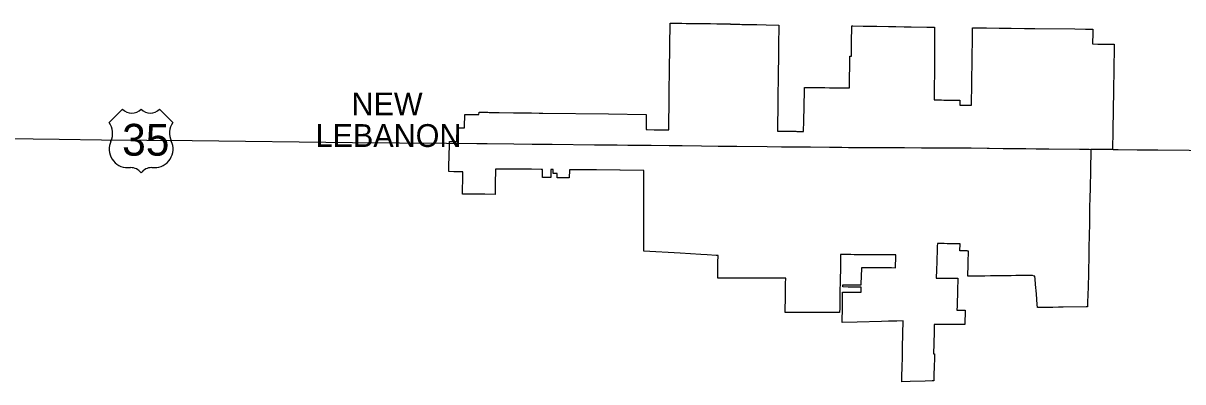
# Model space of a CAD drawing. Extents: x 0 to 34, y 0 to 22.
# Drawn here: x 4.0908 to 4.4993, y 15.0222 to 15.1484 of the extents above; entities that cross this region are included whole.
import ezdxf

# ---------------------------------------------------------------- set-up
doc = ezdxf.new("R2010")
doc.units = 0
for name, color, linetype in [('GM_X_Corporation', 7, 'Continuous'), ('GM_X_Corporation_Text', 7, 'Continuous'), ('GM_X_US_Location', 7, 'Continuous'), ('GM_X_US_Route', 7, 'Continuous'), ('GM_X_US_Shield', 7, 'Continuous')]:
    doc.layers.add(name, color=color, linetype=linetype)

msp = doc.modelspace()

# ---------------------------------------------------------------- linework, layer by layer
at = {"layer": 'GM_X_Corporation'}
for points in [[(4.409102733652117, 15.147058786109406), (4.4118993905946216, 15.147003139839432), (4.411898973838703, 15.146904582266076), (4.411895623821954, 15.146369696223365), (4.411868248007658, 15.141996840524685), (4.411827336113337, 15.135460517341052), (4.41182143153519, 15.134461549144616), (4.411809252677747, 15.132402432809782), (4.411807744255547, 15.132158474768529), (4.411787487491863, 15.128883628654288), (4.411783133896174, 15.12817898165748), (4.411764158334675, 15.125138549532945), (4.411740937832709, 15.121417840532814), (4.411941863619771, 15.121415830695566), (4.4125311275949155, 15.121410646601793), (4.412741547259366, 15.121408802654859), (4.4135492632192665, 15.121401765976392), (4.413945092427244, 15.121397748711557), (4.414198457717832, 15.121395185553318), (4.414342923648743, 15.121393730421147), (4.415142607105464, 15.121386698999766), (4.41594228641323, 15.121379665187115), (4.41674197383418, 15.121372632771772), (4.417143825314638, 15.121368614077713), (4.417395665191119, 15.121366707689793), (4.41754165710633, 15.121365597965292), (4.4183413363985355, 15.12135856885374), (4.419143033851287, 15.121351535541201), (4.419544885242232, 15.121347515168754), (4.419942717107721, 15.121344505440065), (4.420742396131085, 15.121337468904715), (4.420742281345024, 15.121324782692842), (4.420726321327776, 15.119569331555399), (4.42160638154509, 15.11956128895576), (4.42192786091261, 15.119558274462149), (4.423133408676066, 15.119547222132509), (4.424823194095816, 15.119532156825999), (4.424848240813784, 15.122168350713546), (4.424855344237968, 15.122915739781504), (4.424919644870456, 15.122915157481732), (4.4249377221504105, 15.124075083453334), (4.42494925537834, 15.124795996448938), (4.4249505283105, 15.124875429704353), (4.424963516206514, 15.125687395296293), (4.424971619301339, 15.126193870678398), (4.424985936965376, 15.127088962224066), (4.425019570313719, 15.129191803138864), (4.425050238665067, 15.131109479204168), (4.425067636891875, 15.132237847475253), (4.425084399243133, 15.133324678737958), (4.425087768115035, 15.133560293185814), (4.425129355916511, 15.136468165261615), (4.425149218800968, 15.13785689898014), (4.425200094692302, 15.141413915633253), (4.4252264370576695, 15.143255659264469), (4.42524327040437, 15.144432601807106), (4.425254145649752, 15.145192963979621), (4.425277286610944, 15.146810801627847), (4.429326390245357, 15.146763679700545), (4.430103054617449, 15.14675464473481), (4.434657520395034, 15.14670164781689), (4.436739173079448, 15.146677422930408), (4.4388668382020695, 15.14665266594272), (4.443565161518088, 15.146597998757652), (4.445248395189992, 15.146578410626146), (4.447224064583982, 15.146555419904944), (4.461262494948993, 15.14639207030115), (4.465061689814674, 15.14634785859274), (4.467322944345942, 15.146321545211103), (4.467588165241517, 15.14631852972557), (4.467588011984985, 15.146305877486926), (4.467559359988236, 15.143910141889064), (4.467540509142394, 15.14233376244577), (4.46752587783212, 15.141110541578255), (4.469394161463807, 15.141091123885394), (4.469748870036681, 15.141087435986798), (4.470945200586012, 15.14107500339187), (4.472689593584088, 15.14105686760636), (4.475161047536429, 15.141031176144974), (4.475160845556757, 15.141018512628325), (4.475105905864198, 15.137552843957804), (4.475061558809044, 15.134755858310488), (4.47499135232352, 15.130327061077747), (4.47493238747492, 15.126607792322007), (4.4748793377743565, 15.123261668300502), (4.474870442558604, 15.122700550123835), (4.474824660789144, 15.119812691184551), (4.474797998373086, 15.118131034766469), (4.474791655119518, 15.117730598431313), (4.474684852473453, 15.11099382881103), (4.474662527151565, 15.109575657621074), (4.474588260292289, 15.104855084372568), (4.474584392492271, 15.104523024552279), (4.474573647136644, 15.1039300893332), (4.470868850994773, 15.103952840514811), (4.4692145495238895, 15.103962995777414), (4.467061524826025, 15.103986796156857), (4.4669271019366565, 15.10397561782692), (4.466922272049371, 15.103717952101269), (4.466915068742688, 15.103333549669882), (4.466878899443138, 15.101566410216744), (4.466872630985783, 15.101244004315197), (4.466834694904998, 15.099292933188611), (4.466805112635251, 15.097821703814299), (4.466631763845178, 15.089200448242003), (4.466610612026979, 15.088141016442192), (4.466499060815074, 15.082553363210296), (4.466459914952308, 15.080592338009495), (4.466456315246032, 15.080411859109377), (4.466406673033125, 15.077925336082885), (4.4662371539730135, 15.069433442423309), (4.466148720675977, 15.065003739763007), (4.466096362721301, 15.062381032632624), (4.466062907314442, 15.060705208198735), (4.466045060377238, 15.059811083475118), (4.465835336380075, 15.052379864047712), (4.465788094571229, 15.050706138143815), (4.465735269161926, 15.048834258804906), (4.46572960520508, 15.048633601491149), (4.465229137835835, 15.048623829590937), (4.457139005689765, 15.048465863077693), (4.456993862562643, 15.04846312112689), (4.455491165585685, 15.048434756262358), (4.453471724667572, 15.048396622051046), (4.448133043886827, 15.04829582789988), (4.448122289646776, 15.048427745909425), (4.4481147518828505, 15.048520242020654), (4.448053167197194, 15.049275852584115), (4.447738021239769, 15.053142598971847), (4.44747095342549, 15.056419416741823), (4.447310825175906, 15.05838407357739), (4.447238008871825, 15.059277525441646), (4.447231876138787, 15.059352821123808), (4.447021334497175, 15.059349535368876), (4.446966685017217, 15.059348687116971), (4.446412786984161, 15.059631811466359), (4.444787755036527, 15.059612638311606), (4.443867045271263, 15.05960177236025), (4.441094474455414, 15.059569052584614), (4.440538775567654, 15.05956249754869), (4.438841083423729, 15.0595424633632), (4.435899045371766, 15.059507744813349), (4.434672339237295, 15.059493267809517), (4.431599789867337, 15.059457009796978), (4.429552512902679, 15.059432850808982), (4.426803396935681, 15.059400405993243), (4.424186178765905, 15.059369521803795), (4.423548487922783, 15.059361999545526), (4.423558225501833, 15.059651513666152), (4.423675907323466, 15.063212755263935), (4.423720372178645, 15.064661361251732), (4.423815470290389, 15.067759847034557), (4.423829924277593, 15.06823069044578), (4.423543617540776, 15.068237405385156), (4.423308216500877, 15.06824291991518), (4.420819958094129, 15.068296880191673), (4.420806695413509, 15.068297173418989), (4.4208951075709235, 15.070706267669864), (4.419755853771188, 15.070731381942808), (4.418614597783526, 15.070756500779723), (4.418092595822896, 15.07076752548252), (4.417473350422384, 15.070781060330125), (4.416332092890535, 15.07080610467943), (4.415190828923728, 15.070830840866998), (4.414049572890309, 15.070855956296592), (4.413781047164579, 15.070861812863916), (4.412852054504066, 15.070882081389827), (4.412818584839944, 15.069923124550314), (4.412775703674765, 15.068650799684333), (4.412769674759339, 15.068472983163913), (4.412765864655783, 15.068359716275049), (4.412733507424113, 15.067398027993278), (4.412691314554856, 15.066144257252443), (4.412689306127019, 15.066082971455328), (4.41267323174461, 15.065616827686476), (4.412649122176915, 15.064891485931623), (4.412618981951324, 15.06400942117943), (4.412606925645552, 15.063638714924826), (4.412564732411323, 15.06238494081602), (4.412522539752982, 15.06113217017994), (4.412500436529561, 15.060477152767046), (4.412480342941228, 15.059879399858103), (4.412438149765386, 15.058708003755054), (4.412637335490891, 15.058708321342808), (4.413468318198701, 15.05870963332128), (4.413560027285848, 15.058709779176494), (4.414212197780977, 15.058710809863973), (4.414956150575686, 15.05871199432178), (4.415758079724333, 15.058713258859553), (4.416560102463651, 15.058714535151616), (4.417439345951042, 15.058715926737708), (4.418703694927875, 15.058717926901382), (4.420053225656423, 15.05872006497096), (4.420081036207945, 15.058720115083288), (4.4200806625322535, 15.058707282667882), (4.420073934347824, 15.058476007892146), (4.420045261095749, 15.05749016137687), (4.420036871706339, 15.057201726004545), (4.420034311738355, 15.057113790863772), (4.419994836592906, 15.055756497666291), (4.419987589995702, 15.055507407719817), (4.419944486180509, 15.054025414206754), (4.4199162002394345, 15.05305286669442), (4.4198941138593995, 15.052293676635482), (4.4198584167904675, 15.051066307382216), (4.419847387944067, 15.050687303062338), (4.419822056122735, 15.049816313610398), (4.419794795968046, 15.048879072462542), (4.4197527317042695, 15.047432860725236), (4.419765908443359, 15.047432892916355), (4.420883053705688, 15.047435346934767), (4.421293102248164, 15.04743624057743), (4.422478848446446, 15.047435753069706), (4.422636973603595, 15.047436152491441), (4.422494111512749, 15.042315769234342), (4.422330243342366, 15.04232870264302), (4.42058036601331, 15.042330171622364), (4.41929396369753, 15.042331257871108), (4.41915709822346, 15.042331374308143), (4.4180075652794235, 15.042332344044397), (4.416721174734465, 15.042333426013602), (4.415434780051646, 15.042334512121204), (4.414146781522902, 15.042335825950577), (4.4117712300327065, 15.04233825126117), (4.411736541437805, 15.041088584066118), (4.411682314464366, 15.03913489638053), (4.4116043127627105, 15.036324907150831), (4.411598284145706, 15.036083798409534), (4.411587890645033, 15.035711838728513), (4.411483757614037, 15.031984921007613), (4.411855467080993, 15.031983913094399), (4.411799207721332, 15.029947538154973), (4.411746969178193, 15.028045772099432), (4.41173529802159, 15.027625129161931), (4.411654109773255, 15.024698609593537), (4.411632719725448, 15.023927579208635), (4.411594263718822, 15.022541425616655), (4.410997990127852, 15.02252319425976), (4.408604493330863, 15.022450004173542), (4.403270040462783, 15.022287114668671), (4.40034645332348, 15.022197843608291), (4.400380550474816, 15.023776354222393), (4.400386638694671, 15.024058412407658), (4.400459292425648, 15.027521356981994), (4.400527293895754, 15.030762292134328), (4.40057213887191, 15.032878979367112), (4.400603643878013, 15.03436588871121), (4.40079826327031, 15.043598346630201), (4.400798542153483, 15.043611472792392), (4.398609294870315, 15.043557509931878), (4.395666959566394, 15.04348497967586), (4.393132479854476, 15.043422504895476), (4.384600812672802, 15.043212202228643), (4.3792925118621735, 15.043081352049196), (4.3792794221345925, 15.043081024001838), (4.379304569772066, 15.044249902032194), (4.379321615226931, 15.045042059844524), (4.379393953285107, 15.046598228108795), (4.379400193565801, 15.046909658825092), (4.379452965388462, 15.04954267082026), (4.379470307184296, 15.050407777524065), (4.379448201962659, 15.051831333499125), (4.379468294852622, 15.053283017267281), (4.379476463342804, 15.053702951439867), (4.37947834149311, 15.053799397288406), (4.381937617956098, 15.053784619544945), (4.385065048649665, 15.053765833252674), (4.386000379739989, 15.053760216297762), (4.386042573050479, 15.055527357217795), (4.385124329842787, 15.055533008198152), (4.381468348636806, 15.055555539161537), (4.379533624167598, 15.055567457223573), (4.379520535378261, 15.05556754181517), (4.3795378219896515, 15.056335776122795), (4.379538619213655, 15.056371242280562), (4.381179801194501, 15.056361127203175), (4.385854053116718, 15.056332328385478), (4.386060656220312, 15.056331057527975), (4.3860660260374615, 15.056545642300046), (4.386141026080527, 15.059544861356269), (4.386201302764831, 15.061955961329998), (4.386213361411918, 15.062437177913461), (4.388081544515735, 15.06242584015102), (4.38949286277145, 15.062417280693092), (4.393310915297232, 15.062394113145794), (4.396751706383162, 15.062373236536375), (4.398132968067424, 15.062364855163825), (4.398138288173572, 15.062692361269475), (4.398144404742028, 15.063299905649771), (4.3981463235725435, 15.063490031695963), (4.398150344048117, 15.063817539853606), (4.398164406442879, 15.064942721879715), (4.398168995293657, 15.065309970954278), (4.398178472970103, 15.066067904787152), (4.3981885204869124, 15.066878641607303), (4.3972097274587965, 15.06688219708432), (4.396253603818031, 15.066885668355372), (4.395449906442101, 15.066888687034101), (4.394736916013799, 15.06689198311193), (4.394147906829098, 15.06689470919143), (4.3929644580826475, 15.066900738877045), (4.39273540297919, 15.066901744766), (4.3917830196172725, 15.06690676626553), (4.39060157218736, 15.066911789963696), (4.390528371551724, 15.066912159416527), (4.389418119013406, 15.066917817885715), (4.388236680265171, 15.06692384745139), (4.387053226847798, 15.06692987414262), (4.385871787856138, 15.066935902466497), (4.384690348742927, 15.066941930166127), (4.384044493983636, 15.066945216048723), (4.3835068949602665, 15.06694795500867), (4.382325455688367, 15.066953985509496), (4.381202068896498, 15.066959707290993), (4.381142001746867, 15.066960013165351), (4.37967926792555, 15.066967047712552), (4.379191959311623, 15.066960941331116), (4.378716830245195, 15.066954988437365), (4.3787169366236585, 15.066876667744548), (4.378718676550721, 15.065564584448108), (4.378722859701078, 15.062411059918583), (4.37871884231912, 15.06224328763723), (4.37871884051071, 15.06208957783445), (4.378714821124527, 15.0619087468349), (4.378692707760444, 15.061059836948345), (4.378686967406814, 15.060839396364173), (4.378652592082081, 15.059519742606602), (4.378632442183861, 15.058746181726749), (4.378632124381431, 15.058733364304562), (4.3785780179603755, 15.056538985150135), (4.378576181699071, 15.056464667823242), (4.3785440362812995, 15.055036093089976), (4.378529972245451, 15.054442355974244), (4.378511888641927, 15.053725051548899), (4.378503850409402, 15.05331717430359), (4.378491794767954, 15.052454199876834), (4.378483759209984, 15.051830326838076), (4.378505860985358, 15.050406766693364), (4.37848699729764, 15.049495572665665), (4.378485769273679, 15.04943629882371), (4.378485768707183, 15.04940415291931), (4.3784857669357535, 15.049354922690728), (4.378475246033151, 15.048821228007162), (4.3784747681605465, 15.048796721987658), (4.378463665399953, 15.048233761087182), (4.378463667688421, 15.048184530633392), (4.378463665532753, 15.048150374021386), (4.3784295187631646, 15.046596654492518), (4.3767156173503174, 15.046594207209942), (4.376140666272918, 15.046593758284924), (4.375429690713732, 15.046593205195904), (4.374736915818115, 15.04659266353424), (4.374143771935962, 15.04659219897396), (4.373285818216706, 15.046591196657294), (4.372857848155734, 15.04659018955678), (4.372384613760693, 15.046589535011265), (4.371411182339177, 15.046588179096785), (4.370607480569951, 15.046587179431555), (4.368678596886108, 15.046585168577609), (4.366347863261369, 15.046582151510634), (4.364017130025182, 15.046580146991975), (4.362135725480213, 15.046577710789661), (4.361686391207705, 15.04657713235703), (4.360062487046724, 15.046575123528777), (4.359260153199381, 15.04657412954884), (4.359247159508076, 15.04657411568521), (4.359259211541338, 15.04737380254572), (4.3592612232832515, 15.047459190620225), (4.35928712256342, 15.049166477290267), (4.359312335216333, 15.049971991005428), (4.35931547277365, 15.051078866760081), (4.359333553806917, 15.052284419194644), (4.359351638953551, 15.053489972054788), (4.359362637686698, 15.054174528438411), (4.359369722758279, 15.054615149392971), (4.35938981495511, 15.05594929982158), (4.359396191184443, 15.056374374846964), (4.359401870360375, 15.056752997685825), (4.359429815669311, 15.058669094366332), (4.359429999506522, 15.058681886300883), (4.358682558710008, 15.058682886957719), (4.356884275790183, 15.058683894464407), (4.354836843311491, 15.058685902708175), (4.352690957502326, 15.058687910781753), (4.351887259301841, 15.058688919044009), (4.3504426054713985, 15.058689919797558), (4.349202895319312, 15.058690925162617), (4.347965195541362, 15.058691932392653), (4.346197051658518, 15.0586929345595), (4.344869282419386, 15.058693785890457), (4.344637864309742, 15.058693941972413), (4.340078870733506, 15.05869695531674), (4.338543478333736, 15.058698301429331), (4.335497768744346, 15.058700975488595), (4.3355439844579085, 15.062911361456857), (4.335549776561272, 15.06338841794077), (4.335554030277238, 15.063602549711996), (4.33557412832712, 15.064888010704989), (4.335584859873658, 15.06592741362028), (4.335592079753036, 15.066626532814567), (4.335592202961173, 15.06663853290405), (4.335441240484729, 15.066647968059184), (4.3353510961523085, 15.066653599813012), (4.33494924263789, 15.066677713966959), (4.334949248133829, 15.06667816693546), (4.3317364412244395, 15.066874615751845), (4.3295776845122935, 15.067004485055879), (4.32585512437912, 15.067228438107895), (4.32226372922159, 15.067444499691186), (4.309469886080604, 15.068214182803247), (4.309469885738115, 15.07705249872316), (4.309466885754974, 15.089258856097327), (4.309461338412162, 15.090122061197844), (4.309442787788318, 15.093009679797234), (4.309430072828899, 15.09498782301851), (4.3094200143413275, 15.09655261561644), (4.301135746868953, 15.096651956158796), (4.301018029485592, 15.096653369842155), (4.292741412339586, 15.096752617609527), (4.2892687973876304, 15.096794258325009), (4.289172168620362, 15.096795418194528), (4.283243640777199, 15.096866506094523), (4.283242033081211, 15.096747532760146), (4.2832043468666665, 15.093962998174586), (4.279060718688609, 15.094025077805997), (4.2789130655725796, 15.094027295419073), (4.278930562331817, 15.095320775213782), (4.278932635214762, 15.095473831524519), (4.277630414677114, 15.095493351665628), (4.277487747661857, 15.095495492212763), (4.27749862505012, 15.09629913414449), (4.277505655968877, 15.09681845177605), (4.277507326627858, 15.096942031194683), (4.277376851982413, 15.096943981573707), (4.277105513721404, 15.096948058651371), (4.27701534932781, 15.096948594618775), (4.276743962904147, 15.096950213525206), (4.276703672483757, 15.096950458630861), (4.276702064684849, 15.096831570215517), (4.276694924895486, 15.096303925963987), (4.2766645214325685, 15.09405739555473), (4.27655721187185, 15.094058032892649), (4.273771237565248, 15.094074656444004), (4.2738091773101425, 15.096877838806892), (4.273810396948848, 15.096967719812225), (4.27327663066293, 15.096970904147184), (4.273238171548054, 15.09697113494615), (4.269911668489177, 15.096990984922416), (4.269875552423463, 15.09699120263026), (4.267862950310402, 15.097003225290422), (4.26634396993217, 15.097012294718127), (4.266307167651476, 15.097012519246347), (4.257164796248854, 15.097067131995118), (4.257163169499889, 15.096957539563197), (4.2571598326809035, 15.096734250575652), (4.257153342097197, 15.096299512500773), (4.257096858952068, 15.092517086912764), (4.257033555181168, 15.088183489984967), (4.253444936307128, 15.088240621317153), (4.252964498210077, 15.088243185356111), (4.250872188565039, 15.088254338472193), (4.2503979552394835, 15.08825686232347), (4.249910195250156, 15.088259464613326), (4.245573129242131, 15.088282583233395), (4.245687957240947, 15.09508188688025), (4.245704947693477, 15.096088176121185), (4.242652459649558, 15.09614100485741), (4.242572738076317, 15.09614238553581), (4.240752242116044, 15.096173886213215), (4.2407164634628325, 15.096174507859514), (4.2407642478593, 15.097989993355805), (4.240963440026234, 15.105557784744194), (4.24096725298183, 15.105702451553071), (4.24098121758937, 15.106233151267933), (4.2409951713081, 15.106763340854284), (4.24356433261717, 15.106763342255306), (4.243670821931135, 15.111616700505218), (4.244201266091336, 15.111611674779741), (4.245114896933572, 15.111603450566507), (4.246323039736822, 15.111592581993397), (4.246330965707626, 15.112025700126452), (4.246407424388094, 15.116202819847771), (4.2464086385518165, 15.11630015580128), (4.2464961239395, 15.116299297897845), (4.247636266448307, 15.116288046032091), (4.25033065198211, 15.116261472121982), (4.251388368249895, 15.11625104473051), (4.251406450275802, 15.117046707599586), (4.2514069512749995, 15.117094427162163), (4.254058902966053, 15.117058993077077), (4.254501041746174, 15.11705308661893), (4.2550234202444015, 15.117046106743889), (4.2576354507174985, 15.117011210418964), (4.2584988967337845, 15.11699967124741), (4.2635799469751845, 15.116931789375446), (4.264643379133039, 15.116917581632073), (4.264672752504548, 15.116917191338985), (4.265704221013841, 15.116903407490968), (4.266765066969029, 15.116889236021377), (4.26782188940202, 15.116875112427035), (4.269943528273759, 15.116846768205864), (4.2725935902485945, 15.116811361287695), (4.273853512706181, 15.116794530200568), (4.2970512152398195, 15.116484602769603), (4.310311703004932, 15.116307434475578), (4.310309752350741, 15.116163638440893), (4.310309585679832, 15.116150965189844), (4.3102394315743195, 15.110960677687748), (4.310628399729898, 15.110956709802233), (4.313053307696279, 15.110931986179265), (4.31459386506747, 15.110916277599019), (4.314673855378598, 15.110915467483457), (4.316303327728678, 15.110899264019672), (4.318210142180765, 15.110880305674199), (4.318226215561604, 15.112005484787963), (4.318353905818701, 15.121507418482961), (4.318386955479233, 15.123966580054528), (4.318426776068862, 15.12690423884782), (4.318460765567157, 15.12941186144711), (4.318484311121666, 15.131148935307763), (4.318528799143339, 15.134431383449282), (4.318569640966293, 15.137444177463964), (4.31862203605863, 15.14130990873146), (4.318643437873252, 15.14288870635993), (4.318684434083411, 15.145913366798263), (4.318713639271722, 15.148068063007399), (4.3187184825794, 15.148425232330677), (4.319164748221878, 15.148420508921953), (4.322840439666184, 15.148381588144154), (4.324405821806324, 15.148365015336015), (4.326314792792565, 15.148344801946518), (4.328707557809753, 15.148319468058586), (4.328965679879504, 15.148316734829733), (4.329820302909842, 15.148307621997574), (4.332923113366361, 15.148274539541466), (4.335181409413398, 15.148250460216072), (4.338126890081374, 15.148219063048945), (4.339969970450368, 15.1481994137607), (4.339990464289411, 15.148199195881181), (4.339990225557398, 15.148186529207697), (4.339988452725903, 15.148091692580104), (4.340001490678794, 15.148091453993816), (4.343237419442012, 15.148032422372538), (4.343936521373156, 15.148019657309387), (4.347688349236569, 15.147951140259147), (4.349316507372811, 15.147921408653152), (4.352496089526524, 15.147863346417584), (4.356990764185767, 15.147781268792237), (4.35699060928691, 15.147768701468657), (4.35690177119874, 15.140480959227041), (4.356846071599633, 15.13591182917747), (4.356835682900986, 15.135059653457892), (4.356802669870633, 15.132351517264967), (4.3567848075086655, 15.13088634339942), (4.356667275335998, 15.121245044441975), (4.356663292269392, 15.120919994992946), (4.356535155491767, 15.110461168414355), (4.356534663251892, 15.110421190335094), (4.356547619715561, 15.110421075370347), (4.36006915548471, 15.110389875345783), (4.360163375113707, 15.110389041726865), (4.3629583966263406, 15.11036439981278), (4.36335407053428, 15.110360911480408), (4.365716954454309, 15.110339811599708), (4.365801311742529, 15.114028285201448), (4.3658263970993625, 15.115125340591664), (4.365894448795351, 15.118100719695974), (4.365962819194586, 15.121090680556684), (4.366003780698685, 15.122899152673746), (4.366070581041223, 15.12584824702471), (4.37095106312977, 15.125779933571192), (4.373238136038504, 15.125747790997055), (4.374850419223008, 15.125725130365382), (4.377613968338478, 15.125686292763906), (4.38030701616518, 15.125648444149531), (4.381459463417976, 15.125632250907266), (4.381602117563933, 15.1256302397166), (4.3818410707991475, 15.125626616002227), (4.38186734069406, 15.125626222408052), (4.382028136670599, 15.136864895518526), (4.38227495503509, 15.136861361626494), (4.382577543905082, 15.136857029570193), (4.3826437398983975, 15.141483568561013), (4.382729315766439, 15.147464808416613), (4.382994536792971, 15.147460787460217), (4.383127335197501, 15.14745873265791), (4.3867478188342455, 15.147402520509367), (4.388220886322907, 15.147379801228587), (4.389769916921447, 15.147355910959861), (4.391568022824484, 15.147328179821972), (4.395641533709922, 15.14726582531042), (4.397212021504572, 15.147241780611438), (4.397336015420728, 15.147239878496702), (4.398233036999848, 15.147226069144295), (4.401153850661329, 15.14718111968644), (4.403624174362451, 15.147143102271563)], [(4.4118993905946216, 15.147003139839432), (4.411899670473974, 15.147015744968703), (4.411899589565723, 15.147003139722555)]]:
    msp.add_lwpolyline(points, close=True, dxfattribs=at)
at = {"layer": 'GM_X_US_Route'}
for p, q in [((4.239920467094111, 15.1061764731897), (4.250676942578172, 15.10608139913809)), ((4.250676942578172, 15.10608139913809), (4.254259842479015, 15.106043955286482)), ((4.329722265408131, 15.10525708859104), (4.335678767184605, 15.105194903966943)), ((4.379186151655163, 15.104766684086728), (4.38151603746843, 15.104721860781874)), ((4.466349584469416, 15.104063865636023), (4.474793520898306, 15.10394213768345))]:
    msp.add_line(p, q, dxfattribs=at)
for points in [[(4.085226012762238, 15.10779479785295), (4.103569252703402, 15.10757172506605), (4.118419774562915, 15.107399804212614), (4.150398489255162, 15.107085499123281), (4.206823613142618, 15.106469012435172), (4.239920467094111, 15.1061764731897)], [(4.254259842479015, 15.106043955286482), (4.263627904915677, 15.105946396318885), (4.27012817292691, 15.105878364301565), (4.273271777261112, 15.105881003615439), (4.277174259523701, 15.105855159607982), (4.2920696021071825, 15.105649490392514), (4.296513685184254, 15.10564579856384), (4.300062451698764, 15.105588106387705)], [(4.300062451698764, 15.105588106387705), (4.303780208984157, 15.105527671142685), (4.3069417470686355, 15.105494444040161), (4.3120803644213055, 15.105441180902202), (4.318381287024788, 15.105375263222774), (4.322999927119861, 15.105327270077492), (4.329722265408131, 15.10525708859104)], [(4.335678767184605, 15.105194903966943), (4.342269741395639, 15.10512634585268), (4.352850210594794, 15.10505040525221), (4.35798408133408, 15.104962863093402), (4.358736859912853, 15.104954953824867)], [(4.358736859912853, 15.104954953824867), (4.36199888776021, 15.104920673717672), (4.368107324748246, 15.104856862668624), (4.374892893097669, 15.104786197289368), (4.379186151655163, 15.104766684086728)], [(4.38151603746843, 15.104721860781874), (4.386881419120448, 15.104661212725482), (4.391874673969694, 15.104671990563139)], [(4.391874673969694, 15.104671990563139), (4.395920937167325, 15.104680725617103), (4.401069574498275, 15.104669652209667), (4.401326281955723, 15.104666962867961)], [(4.401326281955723, 15.104666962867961), (4.407316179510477, 15.104604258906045), (4.409819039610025, 15.104593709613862), (4.41394512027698, 15.104566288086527), (4.419818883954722, 15.104500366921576), (4.4247027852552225, 15.104507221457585), (4.430367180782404, 15.104442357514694), (4.431045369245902, 15.104452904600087), (4.436012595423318, 15.104367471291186), (4.438553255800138, 15.104345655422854)], [(4.438553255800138, 15.104345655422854), (4.44405803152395, 15.104298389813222), (4.447641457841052, 15.104251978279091), (4.452106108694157, 15.104195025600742), (4.46297479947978, 15.104104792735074)], [(4.46297479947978, 15.104104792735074), (4.464238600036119, 15.104094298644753), (4.466349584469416, 15.104063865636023)], [(4.474793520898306, 15.10394213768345), (4.4765667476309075, 15.103916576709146), (4.483223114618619, 15.103824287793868), (4.490458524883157, 15.10382270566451), (4.501570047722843, 15.103713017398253), (4.509421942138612, 15.103661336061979)]]:
    msp.add_lwpolyline(points, dxfattribs=at)
at = {"layer": 'GM_X_US_Shield'}
for p, q in [((4.125843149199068, 15.118115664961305), (4.121181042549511, 15.113453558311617)), ((4.143559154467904, 15.113453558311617), (4.138897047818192, 15.118115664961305)), ((4.127707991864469, 15.097602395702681), (4.128640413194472, 15.097602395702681)), ((4.136099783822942, 15.097602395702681), (4.137032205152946, 15.097602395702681))]:
    msp.add_line(p, q, dxfattribs=at)
for centre, radius, start, end in [((4.129106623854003, 15.121445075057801), 0.004662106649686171, 225.57299599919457, 314.4270040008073), ((4.135633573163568, 15.121445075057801), 0.004662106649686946, 225.57299599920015, 314.4270040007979), ((4.115834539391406, 15.109709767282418), 0.006526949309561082, 334.5471236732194, 35.000929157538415), ((4.148905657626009, 15.109709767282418), 0.006526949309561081, 144.99907084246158, 205.4528763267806), ((4.127635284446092, 15.104128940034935), 0.006526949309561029, 154.8319194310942, 270.63826363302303), ((4.137104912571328, 15.104128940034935), 0.006526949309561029, 269.36173636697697, 25.168080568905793), ((4.128640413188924, 15.092940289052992), 0.0046621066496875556, 36.86989764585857, 89.99999993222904), ((4.136099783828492, 15.092940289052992), 0.0046621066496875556, 90.00000006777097, 143.13010235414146)]:
    msp.add_arc(centre, radius, start, end, dxfattribs=at)

# ---------------------------------------------------------------- texts
at = {"layer": 'GM_X_Corporation_Text'}
for s, p in [('NEW', (4.206475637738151, 15.11598989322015)), ('LEBANON', (4.193851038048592, 15.104861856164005))]:
    msp.add_text(s, height=0.008037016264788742, rotation=1.0000000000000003e-05, dxfattribs=at).set_placement(p)
at = {"layer": 'GM_X_US_Location'}
for s, p in [('0', (4.13236397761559, 15.107304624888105)), ('/', (4.132365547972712, 15.107304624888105))]:
    msp.add_text(s, height=1.6074032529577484e-05, dxfattribs=at).set_placement(p)
msp.add_text('35', height=1.6074032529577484e-05, rotation=1.0000000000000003e-05, dxfattribs=at).set_placement((4.129046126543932, 15.103977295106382))
at = {"layer": 'GM_X_US_Shield'}
msp.add_text('35', height=0.011189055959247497, dxfattribs=at).set_placement((4.125697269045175, 15.1017982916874))

doc.saveas('drawing.dxf')
